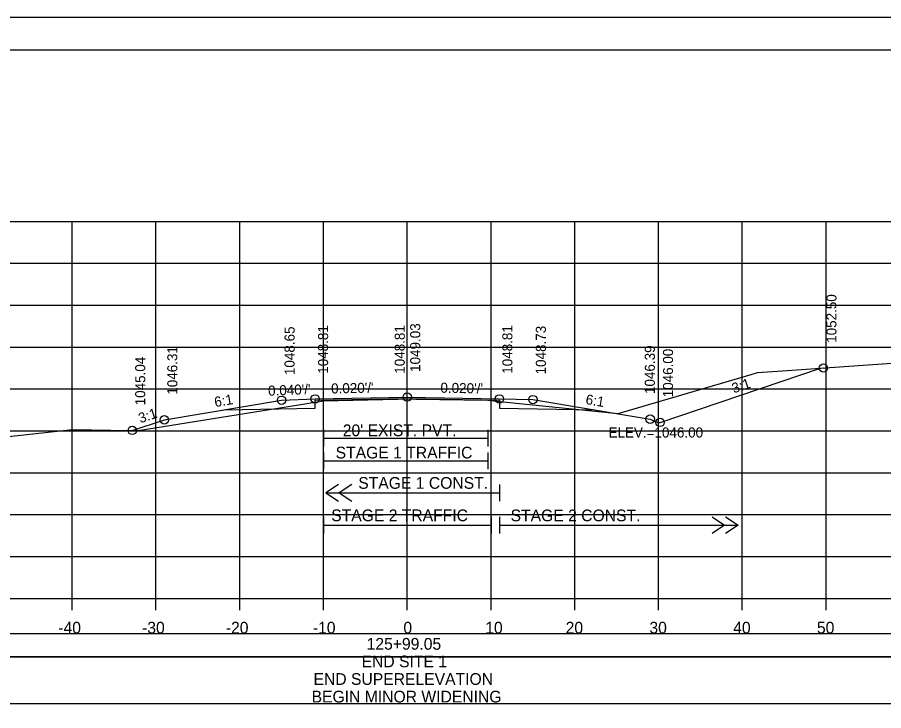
# Model space of a CAD drawing. Extents: x 1370565 to 1374448, y 301010 to 304637.
# Drawn here: x 1370688.5 to 1370791.9, y 303701.1 to 303783.9 of the extents above; entities that cross this region are included whole.
import ezdxf

# ---------------------------------------------------------------- set-up
doc = ezdxf.new("R2010")
doc.units = 0
for name, color, linetype in [('R_Alt Surface', 7, 'Continuous'), ('R_Axis', 7, 'Continuous'), ('R_Axis Annot', 7, 'Continuous'), ('R_Border', 7, 'Continuous'), ('R_Drive', 7, 'Continuous'), ('R_Exist Surface', 7, 'Continuous'), ('R_Fin Surface', 7, 'Continuous'), ('R_Grid', 7, 'Continuous'), ('R_No Plot', 7, 'Continuous'), ('R_Water', 7, 'Continuous'), ('R_Xsect Elev', 7, 'Continuous'), ('R_Xsect Slope', 7, 'Continuous')]:
    doc.layers.add(name, color=color, linetype=linetype)

msp = doc.modelspace()

# ---------------------------------------------------------------- linework, layer by layer
at = {"layer": 'R_Alt Surface'}
for points in [[(1370713.19, 303737.04), (1370724.03, 303737.25), (1370724.02, 303737.25), (1370724.03, 303738.17), (1370735.03, 303738.39), (1370746.03, 303738.17), (1370746.04, 303737.25), (1370746.03, 303737.25), (1370757.41, 303737.03)], [(1370726.82, 303728.13), (1370725.32, 303727.13), (1370726.82, 303726.13)], [(1370728.42, 303728.13), (1370726.92, 303727.13), (1370728.42, 303726.13)], [(1370725.32, 303727.13), (1370746.03, 303727.13)], [(1370725.03, 303724.26), (1370725.03, 303722.26)], [(1370745.03, 303724.26), (1370745.03, 303722.26)], [(1370746.03, 303724.26), (1370746.03, 303722.26)], [(1370746.03, 303724.26), (1370746.03, 303722.26)], [(1370771.42, 303724.26), (1370772.92, 303723.26), (1370771.42, 303722.26)], [(1370773.02, 303724.26), (1370774.52, 303723.26), (1370773.02, 303722.26)], [(1370725.03, 303723.26), (1370745.03, 303723.26)], [(1370746.03, 303723.26), (1370774.52, 303723.26)]]:
    msp.add_lwpolyline(points, dxfattribs=at)
at = {"layer": 'R_Axis'}
for p, q in [((1370585.03, 303714.53), (1370885.03, 303714.53)), ((1370695.03, 303713.13), (1370695.03, 303714.53)), ((1370705.03, 303713.13), (1370705.03, 303714.53)), ((1370715.03, 303713.13), (1370715.03, 303714.53)), ((1370725.03, 303713.13), (1370725.03, 303714.53)), ((1370735.03, 303713.13), (1370735.03, 303714.53)), ((1370745.03, 303713.13), (1370745.03, 303714.53)), ((1370755.03, 303713.13), (1370755.03, 303714.53)), ((1370765.03, 303713.13), (1370765.03, 303714.53)), ((1370775.03, 303713.13), (1370775.03, 303714.53)), ((1370785.03, 303713.13), (1370785.03, 303714.53))]:
    msp.add_line(p, q, dxfattribs=at)
for points in [[(1370725.02, 303734.65), (1370725.02, 303732.65)], [(1370744.65, 303734.65), (1370744.65, 303732.65)], [(1370725.02, 303733.65), (1370744.65, 303733.65)], [(1370725.02, 303731.96), (1370725.02, 303729.96)], [(1370744.65, 303731.96), (1370744.65, 303729.96)], [(1370725.02, 303730.96), (1370744.65, 303730.96)], [(1370746.03, 303728.13), (1370746.03, 303726.13)]]:
    msp.add_lwpolyline(points, dxfattribs=at)
at = {"layer": 'R_Border'}
for p, q in [((1370577.03, 303779.99), (1370893.21, 303779.99)), ((1370729.55, 303779.73), (1370729.55, 303779.73)), ((1370729.55, 303779.73), (1370729.55, 303779.73))]:
    msp.add_line(p, q, dxfattribs=at)
at = {"layer": 'R_Drive'}
for points in [[(1370585.8, 303707.57), (1370884.22, 303707.57), (1370884.22, 303710.28), (1370585.8, 303710.28)], [(1370585.86, 303701.99), (1370884.28, 303701.99), (1370884.28, 303707.52), (1370585.86, 303707.52)]]:
    msp.add_lwpolyline(points, close=True, dxfattribs=at)
at = {"layer": 'R_Exist Surface'}
msp.add_lwpolyline([(1370634.27, 303728.04), (1370695.05, 303734.7), (1370701.86, 303734.57), (1370702.9, 303734.56), (1370722.58, 303737.7), (1370725.01, 303738.1), (1370733.89, 303738.32), (1370734.99, 303738.34), (1370736.07, 303738.32), (1370744.66, 303738.19), (1370746.47, 303737.99), (1370760.22, 303736.61), (1370776.09, 303741.24), (1370776.86, 303741.48), (1370779.23, 303741.65), (1370836.69, 303745.66)], dxfattribs=at)
at = {"layer": 'R_Fin Surface'}
msp.add_lwpolyline([(1370702.2, 303734.57), (1370706.03, 303735.84), (1370720.03, 303738.18), (1370724.03, 303738.34), (1370735.03, 303738.56), (1370746.03, 303738.34), (1370750.03, 303738.26), (1370764.03, 303735.92), (1370764.96, 303735.53), (1370764.97, 303735.53), (1370765.21, 303735.53), (1370784.37, 303742), (1370784.42, 303742.01), (1370784.72, 303742.03)], dxfattribs=at)
at = {"layer": 'R_Grid'}
for p, q in [((1370585.03, 303759.53), (1370885.03, 303759.53)), ((1370695.03, 303714.53), (1370695.03, 303759.53)), ((1370705.03, 303714.53), (1370705.03, 303759.53)), ((1370715.03, 303714.53), (1370715.03, 303759.53)), ((1370725.03, 303714.53), (1370725.03, 303759.53)), ((1370735.03, 303714.53), (1370735.03, 303759.53)), ((1370745.03, 303714.53), (1370745.03, 303759.53)), ((1370755.03, 303714.53), (1370755.03, 303759.53)), ((1370765.03, 303714.53), (1370765.03, 303759.53)), ((1370775.03, 303714.53), (1370775.03, 303759.53)), ((1370785.03, 303714.53), (1370785.03, 303759.53)), ((1370585.03, 303754.53), (1370885.03, 303754.53)), ((1370585.03, 303749.53), (1370885.03, 303749.53)), ((1370585.03, 303744.53), (1370885.03, 303744.53)), ((1370585.03, 303739.53), (1370885.03, 303739.53)), ((1370585.03, 303734.53), (1370885.03, 303734.53)), ((1370585.03, 303729.53), (1370885.03, 303729.53)), ((1370585.03, 303724.53), (1370885.03, 303724.53)), ((1370585.03, 303719.53), (1370885.03, 303719.53)), ((1370585.03, 303714.53), (1370885.03, 303714.53))]:
    msp.add_line(p, q, dxfattribs=at)
at = {"layer": 'R_No Plot'}
msp.add_line((1370564.63, 303783.89), (1370897.96, 303783.89), dxfattribs=at)
for points in [[(1370564.62, 303783.89), (1370897.96, 303783.89), (1370897.96, 303570.55), (1370564.62, 303570.55)], [(1370810.95, 303779.99), (1370830.57, 303779.99), (1370830.57, 303770.11), (1370846.68, 303770.11), (1370869.88, 303770.11), (1370869.88, 303737.44), (1370893.09, 303737.44), (1370893.21, 303574.53), (1370577.03, 303574.53), (1370577.03, 303779.99)]]:
    msp.add_lwpolyline(points, close=True, dxfattribs=at)
for centre in [(1370784.72, 303742.03), (1370720.03, 303738.18), (1370724.03, 303738.34), (1370735.03, 303738.56), (1370746.03, 303738.34), (1370750.03, 303738.26), (1370706.03, 303735.84), (1370764.03, 303735.92), (1370765.21, 303735.53), (1370702.2, 303734.57)]:
    msp.add_circle(centre, 0.5, dxfattribs=at)
at = {"layer": 'R_Xsect Elev'}
msp.add_line((1370735.03, 303738.34), (1370735.03, 303748.34), dxfattribs=at)

# ---------------------------------------------------------------- texts
at = {"layer": 'R_Axis Annot'}
for s, p in [("20' EXIST. PVT.", (1370727.33, 303733.89)), ('-40', (1370693.37, 303710.33)), ('-30', (1370703.37, 303710.33)), ('-20', (1370713.37, 303710.33)), ('-10', (1370723.76, 303710.33)), ('0', (1370734.57, 303710.33)), ('10', (1370744.34, 303710.33)), ('20', (1370753.94, 303710.33)), ('30', (1370763.94, 303710.33)), ('40', (1370773.94, 303710.33)), ('50', (1370783.94, 303710.33)), ('125+99.05', (1370730.18, 303708.4)), ('END SITE 1', (1370729.58, 303706.3)), ('END SUPERELEVATION', (1370723.84, 303704.2)), ('BEGIN MINOR WIDENING', (1370723.61, 303702.1))]:
    msp.add_text(s, height=1.4, dxfattribs=at).set_placement(p)
at = {"layer": 'R_Water'}
for s, p in [('STAGE 1 TRAFFIC', (1370726.48, 303731.23)), ('STAGE 1 CONST.', (1370729.18, 303727.61)), ('STAGE 2 TRAFFIC', (1370725.95, 303723.74)), ('STAGE 2 CONST.', (1370747.37, 303723.73))]:
    msp.add_text(s, height=1.4, dxfattribs=at).set_placement(p)
at = {"layer": 'R_Xsect Elev'}
for s, p in [('1052.50', (1370786.27, 303745.03)), ('1048.65', (1370721.58, 303741.18)), ('1048.81', (1370725.58, 303741.34)), ('1048.81', (1370734.73, 303741.34)), ('1049.03', (1370736.58, 303741.56)), ('1048.81', (1370747.58, 303741.34)), ('1048.73', (1370751.58, 303741.26)), ('1046.31', (1370707.58, 303738.84)), ('1046.39', (1370764.59, 303738.92)), ('1046.00', (1370766.76, 303738.53)), ('1045.04', (1370703.75, 303737.57))]:
    msp.add_text(s, height=1.2, rotation=90, dxfattribs=at).set_placement(p)
msp.add_text('ELEV.=1046.00', height=1.2, dxfattribs=at).set_placement((1370759.06, 303733.73))
at = {"layer": 'R_Xsect Slope'}
for s, rotation, p in [("0.020'/'", 1.1458, (1370725.95, 303738.98)), ('3:1', 18.4332, (1370774.01, 303738.99)), ("0.040'/'", 2.2906, (1370718.44, 303738.71)), ("0.020'/'", 358.8542, (1370738.98, 303739.08)), ('6:1', 9.4642, (1370712.1, 303737.36)), ('6:1', 350.5358, (1370756.26, 303737.73)), ('3:1', 18.4349, (1370703.17, 303735.42))]:
    msp.add_text(s, height=1.2, rotation=rotation, dxfattribs=at).set_placement(p)

doc.saveas('drawing.dxf')
